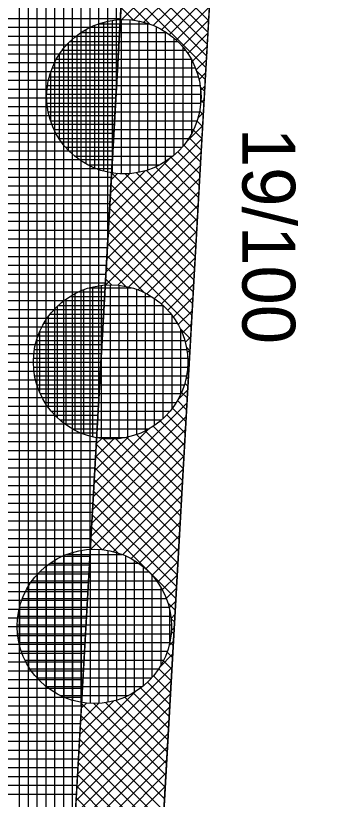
# Model space of a CAD drawing. Extents: x -565346 to -564154, y -1097386 to -1095620.
# Drawn here: x -564292.48 to -564285.01, y -1097217.11 to -1097199.33 of the extents above; entities that cross this region are included whole.
import ezdxf

# ---------------------------------------------------------------- set-up
doc = ezdxf.new("R2010")
doc.units = 0
for name, color, linetype in [('Vrstva 13', 7, 'Continuous'), ('Vrstva 40', 7, 'Continuous'), ('Vrstva 41', 7, 'Continuous'), ('Vrstva 42', 7, 'Continuous'), ('Vrstva 43', 7, 'Continuous'), ('Vrstva 44', 7, 'Continuous')]:
    doc.layers.add(name, color=color, linetype=linetype)

msp = doc.modelspace()

# ---------------------------------------------------------------- linework, layer by layer
at = {"layer": 'Vrstva 13'}
msp.add_line((-564287.03, -1097180.53), (-564291.2, -1097253.99), dxfattribs=at)
at = {"layer": 'Vrstva 41'}
msp.add_lwpolyline([(-564297.082, -1097322.329), (-564302.848, -1097333.175), (-564300.817, -1097333.615), (-564295.11, -1097322.88), (-564285.364, -1097151.156), (-564287.358, -1097151.043), (-564289.027, -1097180.417), (-564293.197, -1097253.877), (-564296.237, -1097307.437)], close=True, dxfattribs=at)
at = {"layer": 'Vrstva 42'}
for p, q in [((-564287.985, -1097197.326), (-564290.076, -1097199.417)), ((-564289.999, -1097197.539), (-564288.104, -1097199.434)), ((-564288.002, -1097197.626), (-564289.806, -1097199.429)), ((-564290.014, -1097197.807), (-564288.119, -1097199.702)), ((-564288.019, -1097197.925), (-564289.57, -1097199.476)), ((-564290.029, -1097198.075), (-564288.135, -1097199.969)), ((-564290.045, -1097198.342), (-564288.15, -1097200.237)), ((-564288.036, -1097198.225), (-564289.358, -1097199.548)), ((-564288.053, -1097198.525), (-564289.167, -1097199.639)), ((-564290.06, -1097198.61), (-564288.165, -1097200.505)), ((-564290.075, -1097198.878), (-564289.434, -1097199.519)), ((-564288.07, -1097198.825), (-564288.994, -1097199.749)), ((-564290.09, -1097199.145), (-564289.806, -1097199.429)), ((-564288.087, -1097199.125), (-564288.839, -1097199.878)), ((-564290.105, -1097199.413), (-564290.1, -1097199.418)), ((-564288.104, -1097199.425), (-564288.701, -1097200.022)), ((-564288.121, -1097199.725), (-564288.578, -1097200.182)), ((-564288.138, -1097200.024), (-564288.472, -1097200.359)), ((-564288.155, -1097200.324), (-564288.386, -1097200.555)), ((-564288.379, -1097200.574), (-564288.18, -1097200.772)), ((-564288.172, -1097200.624), (-564288.32, -1097200.772)), ((-564288.289, -1097200.946), (-564288.195, -1097201.04)), ((-564288.189, -1097200.924), (-564288.282, -1097201.017)), ((-564288.206, -1097201.224), (-564288.281, -1097201.299)), ((-564288.278, -1097201.24), (-564288.211, -1097201.308)), ((-564288.223, -1097201.524), (-564288.344, -1097201.644)), ((-564288.307, -1097201.494), (-564288.226, -1097201.575)), ((-564288.365, -1097201.719), (-564288.241, -1097201.843)), ((-564288.24, -1097201.824), (-564288.606, -1097202.189)), ((-564288.447, -1097201.92), (-564288.256, -1097202.111)), ((-564288.257, -1097202.123), (-564290.38, -1097204.246)), ((-564288.548, -1097202.101), (-564288.271, -1097202.378)), ((-564288.274, -1097202.423), (-564290.397, -1097204.546)), ((-564288.802, -1097202.413), (-564288.302, -1097202.914)), ((-564288.667, -1097202.265), (-564288.287, -1097202.646)), ((-564288.999, -1097202.582), (-564290.363, -1097203.946)), ((-564288.953, -1097202.545), (-564288.317, -1097203.181)), ((-564288.291, -1097202.723), (-564290.414, -1097204.846)), ((-564289.305, -1097202.759), (-564288.347, -1097203.717)), ((-564289.12, -1097202.661), (-564288.332, -1097203.449)), ((-564289.544, -1097202.844), (-564290.346, -1097203.647)), ((-564289.889, -1097202.907), (-564290.329, -1097203.347)), ((-564290.164, -1097202.899), (-564290.312, -1097203.047)), ((-564290.303, -1097202.892), (-564288.408, -1097204.787)), ((-564290, -1097202.913), (-564288.393, -1097204.52)), ((-564289.741, -1097202.889), (-564288.378, -1097204.252)), ((-564289.511, -1097202.836), (-564288.362, -1097203.984)), ((-564288.308, -1097203.023), (-564290.431, -1097205.146)), ((-564288.325, -1097203.323), (-564290.443, -1097205.44)), ((-564290.318, -1097203.16), (-564288.423, -1097205.055)), ((-564290.333, -1097203.428), (-564288.438, -1097205.323)), ((-564288.342, -1097203.623), (-564290.162, -1097205.443)), ((-564290.348, -1097203.695), (-564288.454, -1097205.59)), ((-564290.364, -1097203.963), (-564288.469, -1097205.858)), ((-564288.359, -1097203.923), (-564289.919, -1097205.483)), ((-564290.379, -1097204.231), (-564288.484, -1097206.125)), ((-564288.376, -1097204.222), (-564289.704, -1097205.55)), ((-564290.394, -1097204.498), (-564288.499, -1097206.393)), ((-564288.393, -1097204.522), (-564289.508, -1097205.638)), ((-564290.409, -1097204.766), (-564289.568, -1097205.608)), ((-564288.41, -1097204.822), (-564289.332, -1097205.744)), ((-564290.424, -1097205.034), (-564289.991, -1097205.467)), ((-564288.427, -1097205.122), (-564289.173, -1097205.868)), ((-564290.44, -1097205.301), (-564290.306, -1097205.435)), ((-564288.444, -1097205.422), (-564289.03, -1097206.007)), ((-564288.461, -1097205.722), (-564288.903, -1097206.163)), ((-564288.478, -1097206.022), (-564288.794, -1097206.337)), ((-564288.495, -1097206.321), (-564288.703, -1097206.53)), ((-564288.748, -1097206.428), (-564288.514, -1097206.661)), ((-564288.512, -1097206.621), (-564288.633, -1097206.742)), ((-564288.607, -1097206.851), (-564288.53, -1097206.928)), ((-564288.529, -1097206.921), (-564288.587, -1097206.979)), ((-564288.546, -1097207.221), (-564288.578, -1097207.253)), ((-564288.575, -1097207.166), (-564288.545, -1097207.196)), ((-564288.563, -1097207.521), (-564288.62, -1097207.578)), ((-564288.594, -1097207.43), (-564288.56, -1097207.464)), ((-564288.643, -1097207.663), (-564288.575, -1097207.731)), ((-564288.58, -1097207.821), (-564288.797, -1097208.038)), ((-564288.716, -1097207.873), (-564288.59, -1097207.999)), ((-564288.597, -1097208.121), (-564290.72, -1097210.244)), ((-564288.81, -1097208.062), (-564288.606, -1097208.267)), ((-564288.923, -1097208.232), (-564288.621, -1097208.534)), ((-564288.614, -1097208.421), (-564290.737, -1097210.543)), ((-564289.053, -1097208.384), (-564288.636, -1097208.802)), ((-564289.361, -1097208.643), (-564288.666, -1097209.337)), ((-564289.199, -1097208.522), (-564288.651, -1097209.07)), ((-564288.631, -1097208.72), (-564290.754, -1097210.843)), ((-564289.47, -1097208.711), (-564290.703, -1097209.944)), ((-564289.738, -1097208.831), (-564288.697, -1097209.873)), ((-564289.54, -1097208.746), (-564288.681, -1097209.605)), ((-564289.93, -1097208.888), (-564290.686, -1097209.644)), ((-564290.255, -1097208.93), (-564290.669, -1097209.344)), ((-564290.521, -1097208.913), (-564290.652, -1097209.044)), ((-564290.502, -1097208.915), (-564288.742, -1097210.676)), ((-564290.207, -1097208.928), (-564288.727, -1097210.408)), ((-564289.957, -1097208.895), (-564288.712, -1097210.14)), ((-564288.648, -1097209.02), (-564290.771, -1097211.143)), ((-564290.652, -1097209.048), (-564288.757, -1097210.943)), ((-564288.665, -1097209.32), (-564290.784, -1097211.439)), ((-564290.667, -1097209.316), (-564288.773, -1097211.211)), ((-564290.683, -1097209.584), (-564288.788, -1097211.479)), ((-564288.682, -1097209.62), (-564290.507, -1097211.445)), ((-564290.698, -1097209.851), (-564288.803, -1097211.746)), ((-564288.699, -1097209.92), (-564290.268, -1097211.489)), ((-564290.713, -1097210.119), (-564288.818, -1097212.014)), ((-564288.716, -1097210.22), (-564290.054, -1097211.558)), ((-564290.728, -1097210.387), (-564288.833, -1097212.282)), ((-564288.733, -1097210.52), (-564289.861, -1097211.647)), ((-564290.743, -1097210.654), (-564288.849, -1097212.549)), ((-564290.759, -1097210.922), (-564290.163, -1097211.517)), ((-564288.75, -1097210.819), (-564289.686, -1097211.755)), ((-564288.767, -1097211.119), (-564289.528, -1097211.88)), ((-564290.774, -1097211.19), (-564290.52, -1097211.444)), ((-564288.784, -1097211.419), (-564289.387, -1097212.022)), ((-564288.801, -1097211.719), (-564289.262, -1097212.18)), ((-564288.818, -1097212.019), (-564289.155, -1097212.355)), ((-564288.835, -1097212.319), (-564289.066, -1097212.549)), ((-564289.027, -1097212.653), (-564288.864, -1097212.817)), ((-564288.853, -1097212.619), (-564288.997, -1097212.763)), ((-564288.87, -1097212.918), (-564288.954, -1097213.003)), ((-564288.954, -1097213.01), (-564288.879, -1097213.084)), ((-564288.887, -1097213.218), (-564288.949, -1097213.281)), ((-564288.95, -1097213.296), (-564288.894, -1097213.352)), ((-564288.904, -1097213.518), (-564289, -1097213.615)), ((-564288.982, -1097213.547), (-564288.909, -1097213.62)), ((-564288.921, -1097213.818), (-564289.208, -1097214.106)), ((-564289.046, -1097213.766), (-564288.925, -1097213.887)), ((-564289.13, -1097213.965), (-564288.94, -1097214.155)), ((-564288.938, -1097214.118), (-564291.061, -1097216.241)), ((-564289.233, -1097214.144), (-564288.955, -1097214.423)), ((-564289.354, -1097214.306), (-564288.97, -1097214.69)), ((-564288.955, -1097214.418), (-564291.078, -1097216.541)), ((-564289.491, -1097214.452), (-564288.985, -1097214.958)), ((-564289.772, -1097214.67), (-564291.044, -1097215.941)), ((-564289.813, -1097214.696), (-564289.016, -1097215.493)), ((-564289.644, -1097214.583), (-564289, -1097215.226)), ((-564288.972, -1097214.718), (-564291.095, -1097216.841)), ((-564290.263, -1097214.878), (-564291.027, -1097215.641)), ((-564290.211, -1097214.864), (-564289.046, -1097216.029)), ((-564290.001, -1097214.79), (-564289.031, -1097215.761)), ((-564288.989, -1097215.017), (-564291.112, -1097217.14)), ((-564290.597, -1097214.929), (-564291.009, -1097215.341)), ((-564290.867, -1097214.916), (-564290.992, -1097215.041)), ((-564290.987, -1097214.937), (-564289.092, -1097216.832)), ((-564290.708, -1097214.933), (-564289.076, -1097216.564)), ((-564290.444, -1097214.914), (-564289.061, -1097216.296)), ((-564291.002, -1097215.204), (-564289.107, -1097217.099)), ((-564289.006, -1097215.317), (-564291.117, -1097217.429)), ((-564291.017, -1097215.472), (-564289.122, -1097217.367)), ((-564291.032, -1097215.74), (-564289.137, -1097217.635)), ((-564289.023, -1097215.617), (-564290.841, -1097217.436)), ((-564289.04, -1097215.917), (-564290.603, -1097217.48)), ((-564291.047, -1097216.007), (-564289.152, -1097217.902)), ((-564291.062, -1097216.275), (-564289.168, -1097218.17)), ((-564289.057, -1097216.217), (-564290.389, -1097217.549)), ((-564291.078, -1097216.543), (-564289.183, -1097218.438)), ((-564289.074, -1097216.517), (-564290.196, -1097217.639)), ((-564291.093, -1097216.81), (-564290.332, -1097217.571)), ((-564289.091, -1097216.817), (-564290.021, -1097217.747)), ((-564291.108, -1097217.078), (-564290.734, -1097217.452))]:
    msp.add_line(p, q, dxfattribs=at)
at = {"layer": 'Vrstva 43'}
for p, q in [((-564290.19, -1097200.905), (-564290.19, -1097068.547)), ((-564290.39, -1097204.428), (-564290.39, -1097072.067)), ((-564290.59, -1097207.951), (-564290.59, -1097075.587)), ((-564290.79, -1097211.475), (-564290.79, -1097079.106)), ((-564290.99, -1097214.998), (-564290.99, -1097082.626)), ((-564291.19, -1097218.521), (-564291.19, -1097086.146)), ((-564291.39, -1097222.044), (-564291.39, -1097089.666)), ((-564291.59, -1097225.568), (-564291.59, -1097093.186)), ((-564291.79, -1097229.091), (-564291.79, -1097096.706)), ((-564291.99, -1097232.614), (-564291.99, -1097100.226)), ((-564292.19, -1097236.137), (-564292.19, -1097103.746)), ((-564292.39, -1097239.661), (-564292.39, -1097107.266)), ((-564297.114, -1097199.39), (-564290.104, -1097199.39)), ((-564297.126, -1097199.59), (-564290.115, -1097199.59)), ((-564297.137, -1097199.79), (-564290.127, -1097199.79)), ((-564297.148, -1097199.99), (-564290.138, -1097199.99)), ((-564297.16, -1097200.19), (-564290.149, -1097200.19)), ((-564297.171, -1097200.39), (-564290.161, -1097200.39)), ((-564297.182, -1097200.59), (-564290.172, -1097200.59)), ((-564297.194, -1097200.79), (-564290.183, -1097200.79)), ((-564297.205, -1097200.99), (-564290.195, -1097200.99)), ((-564297.217, -1097201.19), (-564290.206, -1097201.19)), ((-564297.228, -1097201.39), (-564290.218, -1097201.39)), ((-564297.239, -1097201.59), (-564290.229, -1097201.59)), ((-564297.251, -1097201.79), (-564290.24, -1097201.79)), ((-564297.262, -1097201.99), (-564290.252, -1097201.99)), ((-564297.273, -1097202.19), (-564290.263, -1097202.19)), ((-564297.285, -1097202.39), (-564290.274, -1097202.39)), ((-564297.296, -1097202.59), (-564290.286, -1097202.59)), ((-564297.307, -1097202.79), (-564290.297, -1097202.79)), ((-564297.319, -1097202.99), (-564290.308, -1097202.99)), ((-564297.33, -1097203.19), (-564290.32, -1097203.19)), ((-564297.341, -1097203.39), (-564290.331, -1097203.39)), ((-564297.353, -1097203.59), (-564290.342, -1097203.59)), ((-564297.364, -1097203.79), (-564290.354, -1097203.79)), ((-564297.376, -1097203.99), (-564290.365, -1097203.99)), ((-564297.387, -1097204.19), (-564290.376, -1097204.19)), ((-564297.398, -1097204.39), (-564290.388, -1097204.39)), ((-564297.41, -1097204.59), (-564290.399, -1097204.59)), ((-564297.421, -1097204.79), (-564290.411, -1097204.79)), ((-564297.432, -1097204.99), (-564290.422, -1097204.99)), ((-564297.444, -1097205.19), (-564290.433, -1097205.19)), ((-564297.455, -1097205.39), (-564290.445, -1097205.39)), ((-564297.466, -1097205.59), (-564290.456, -1097205.59)), ((-564297.478, -1097205.79), (-564290.467, -1097205.79)), ((-564297.489, -1097205.99), (-564290.479, -1097205.99)), ((-564297.5, -1097206.19), (-564290.49, -1097206.19)), ((-564297.512, -1097206.39), (-564290.501, -1097206.39)), ((-564297.523, -1097206.59), (-564290.513, -1097206.59)), ((-564297.534, -1097206.79), (-564290.524, -1097206.79)), ((-564297.546, -1097206.99), (-564290.535, -1097206.99)), ((-564297.557, -1097207.19), (-564290.547, -1097207.19)), ((-564297.569, -1097207.39), (-564290.558, -1097207.39)), ((-564297.58, -1097207.59), (-564290.569, -1097207.59)), ((-564297.591, -1097207.79), (-564290.581, -1097207.79)), ((-564297.603, -1097207.99), (-564290.592, -1097207.99)), ((-564297.614, -1097208.19), (-564290.604, -1097208.19)), ((-564297.625, -1097208.39), (-564290.615, -1097208.39)), ((-564297.637, -1097208.59), (-564290.626, -1097208.59)), ((-564297.648, -1097208.79), (-564290.638, -1097208.79)), ((-564297.659, -1097208.99), (-564290.649, -1097208.99)), ((-564297.671, -1097209.19), (-564290.66, -1097209.19)), ((-564297.682, -1097209.39), (-564290.672, -1097209.39)), ((-564297.693, -1097209.59), (-564290.683, -1097209.59)), ((-564297.705, -1097209.79), (-564290.694, -1097209.79)), ((-564297.716, -1097209.99), (-564290.706, -1097209.99)), ((-564297.728, -1097210.19), (-564290.717, -1097210.19)), ((-564297.739, -1097210.39), (-564290.728, -1097210.39)), ((-564297.75, -1097210.59), (-564290.74, -1097210.59)), ((-564297.762, -1097210.79), (-564290.751, -1097210.79)), ((-564297.773, -1097210.99), (-564290.762, -1097210.99)), ((-564297.784, -1097211.19), (-564290.774, -1097211.19)), ((-564297.796, -1097211.39), (-564290.785, -1097211.39)), ((-564297.807, -1097211.59), (-564290.797, -1097211.59)), ((-564297.818, -1097211.79), (-564290.808, -1097211.79)), ((-564297.83, -1097211.99), (-564290.819, -1097211.99)), ((-564297.841, -1097212.19), (-564290.831, -1097212.19)), ((-564297.852, -1097212.39), (-564290.842, -1097212.39)), ((-564297.864, -1097212.59), (-564290.853, -1097212.59)), ((-564297.875, -1097212.79), (-564290.865, -1097212.79)), ((-564297.886, -1097212.99), (-564290.876, -1097212.99)), ((-564297.898, -1097213.19), (-564290.887, -1097213.19)), ((-564297.909, -1097213.39), (-564290.899, -1097213.39)), ((-564297.921, -1097213.59), (-564290.91, -1097213.59)), ((-564297.932, -1097213.79), (-564290.921, -1097213.79)), ((-564297.943, -1097213.99), (-564290.933, -1097213.99)), ((-564297.955, -1097214.19), (-564290.944, -1097214.19)), ((-564297.966, -1097214.39), (-564290.955, -1097214.39)), ((-564297.977, -1097214.59), (-564290.967, -1097214.59)), ((-564297.989, -1097214.79), (-564290.978, -1097214.79)), ((-564298, -1097214.99), (-564290.99, -1097214.99)), ((-564298.011, -1097215.19), (-564291.001, -1097215.19)), ((-564298.023, -1097215.39), (-564291.012, -1097215.39)), ((-564298.034, -1097215.59), (-564291.024, -1097215.59)), ((-564298.045, -1097215.79), (-564291.035, -1097215.79)), ((-564298.057, -1097215.99), (-564291.046, -1097215.99)), ((-564298.068, -1097216.19), (-564291.058, -1097216.19)), ((-564298.08, -1097216.39), (-564291.069, -1097216.39)), ((-564298.091, -1097216.59), (-564291.08, -1097216.59)), ((-564298.102, -1097216.79), (-564291.092, -1097216.79)), ((-564298.114, -1097216.99), (-564291.103, -1097216.99))]:
    msp.add_line(p, q, dxfattribs=at)
msp.add_lwpolyline([(-564283.37, -1096906.18), (-564284.87, -1096930.83), (-564282.373, -1096930.972), (-564294.286, -1097140.634), (-564296.782, -1097140.492), (-564297.42, -1097150.37), (-564294.347, -1097150.646), (-564303.226, -1097307.04), (-564304.096, -1097322.37), (-564304.399, -1097332.838), (-564302.848, -1097333.175), (-564297.082, -1097322.329), (-564293.197, -1097253.877), (-564289.027, -1097180.417), (-564287.358, -1097151.043), (-564285.364, -1097151.156), (-564284.798, -1097141.172), (-564286.791, -1097141.059), (-564274.888, -1096931.397), (-564272.899, -1096931.51), (-564271.475, -1096906.55)], dxfattribs=at)
at = {"layer": 'Vrstva 44'}
for p, q in [((-564290.69, -1097199.546), (-564290.69, -1097202.783)), ((-564290.593, -1097199.51), (-564289.46, -1097199.51)), ((-564290.49, -1097199.477), (-564290.49, -1097202.851)), ((-564290.29, -1097199.435), (-564290.29, -1097202.892)), ((-564290.09, -1097199.417), (-564290.09, -1097202.912)), ((-564289.89, -1097199.421), (-564289.89, -1097202.908)), ((-564289.69, -1097199.447), (-564289.69, -1097202.879)), ((-564289.49, -1097199.499), (-564289.49, -1097202.828)), ((-564289.29, -1097199.579), (-564289.29, -1097202.75)), ((-564290.998, -1097199.71), (-564289.053, -1097199.71)), ((-564290.89, -1097199.644), (-564290.89, -1097202.684)), ((-564289.09, -1097199.687), (-564289.09, -1097202.641)), ((-564291.245, -1097199.91), (-564288.807, -1097199.91)), ((-564291.09, -1097199.774), (-564291.09, -1097202.552)), ((-564288.89, -1097199.835), (-564288.89, -1097202.492)), ((-564291.422, -1097200.11), (-564288.632, -1097200.11)), ((-564291.29, -1097199.956), (-564291.29, -1097202.372)), ((-564288.69, -1097200.035), (-564288.69, -1097202.291)), ((-564291.49, -1097200.208), (-564291.49, -1097202.12)), ((-564291.552, -1097200.31), (-564288.5, -1097200.31)), ((-564288.49, -1097200.327), (-564288.49, -1097201.997)), ((-564291.69, -1097200.626), (-564291.69, -1097201.704)), ((-564291.648, -1097200.51), (-564288.405, -1097200.51)), ((-564291.716, -1097200.71), (-564288.339, -1097200.71)), ((-564291.758, -1097200.91), (-564288.297, -1097200.91)), ((-564288.29, -1097200.948), (-564288.29, -1097201.363)), ((-564291.774, -1097201.11), (-564288.278, -1097201.11)), ((-564291.768, -1097201.31), (-564288.284, -1097201.31)), ((-564291.74, -1097201.51), (-564288.313, -1097201.51)), ((-564291.688, -1097201.71), (-564288.366, -1097201.71)), ((-564291.608, -1097201.91), (-564288.445, -1097201.91)), ((-564291.496, -1097202.11), (-564288.556, -1097202.11)), ((-564291.349, -1097202.31), (-564288.706, -1097202.31)), ((-564291.143, -1097202.51), (-564288.911, -1097202.51)), ((-564290.845, -1097202.71), (-564289.211, -1097202.71)), ((-564290.118, -1097202.91), (-564289.914, -1097202.91)), ((-564290.54, -1097205.449), (-564290.54, -1097208.921)), ((-564290.34, -1097205.435), (-564290.34, -1097208.932)), ((-564290.14, -1097205.444), (-564290.14, -1097208.922)), ((-564291.14, -1097205.636), (-564291.14, -1097208.733)), ((-564290.94, -1097205.546), (-564290.94, -1097208.821)), ((-564290.802, -1097205.5), (-564289.856, -1097205.5)), ((-564290.74, -1097205.485), (-564290.74, -1097208.883)), ((-564289.94, -1097205.478), (-564289.94, -1097208.889)), ((-564289.74, -1097205.537), (-564289.74, -1097208.832)), ((-564289.54, -1097205.622), (-564289.54, -1097208.746)), ((-564291.34, -1097205.76), (-564291.34, -1097208.608)), ((-564291.254, -1097205.7), (-564289.402, -1097205.7)), ((-564289.34, -1097205.739), (-564289.34, -1097208.627)), ((-564291.54, -1097205.925), (-564291.54, -1097208.445)), ((-564291.515, -1097205.9), (-564289.14, -1097205.9)), ((-564289.14, -1097205.9), (-564289.14, -1097208.469)), ((-564291.74, -1097206.152), (-564291.74, -1097208.214)), ((-564291.698, -1097206.1), (-564288.955, -1097206.1)), ((-564288.94, -1097206.119), (-564288.94, -1097208.25)), ((-564291.836, -1097206.3), (-564288.818, -1097206.3)), ((-564291.94, -1097206.512), (-564291.94, -1097207.857)), ((-564291.935, -1097206.5), (-564288.716, -1097206.5)), ((-564288.74, -1097206.449), (-564288.74, -1097207.92)), ((-564292.006, -1097206.7), (-564288.647, -1097206.7)), ((-564292.052, -1097206.9), (-564288.602, -1097206.9)), ((-564292.074, -1097207.1), (-564288.58, -1097207.1)), ((-564292.071, -1097207.3), (-564288.58, -1097207.3)), ((-564292.046, -1097207.5), (-564288.606, -1097207.5)), ((-564291.997, -1097207.7), (-564288.656, -1097207.7)), ((-564291.923, -1097207.9), (-564288.732, -1097207.9)), ((-564291.815, -1097208.1), (-564288.836, -1097208.1)), ((-564291.673, -1097208.3), (-564288.981, -1097208.3)), ((-564291.477, -1097208.5), (-564289.175, -1097208.5)), ((-564291.196, -1097208.7), (-564289.455, -1097208.7)), ((-564290.661, -1097208.9), (-564289.993, -1097208.9)), ((-564291.19, -1097211.506), (-564291.19, -1097214.863)), ((-564290.99, -1097211.459), (-564290.99, -1097214.907)), ((-564290.79, -1097211.438), (-564290.79, -1097214.93)), ((-564290.59, -1097211.439), (-564290.59, -1097214.93)), ((-564290.39, -1097211.463), (-564290.39, -1097214.906)), ((-564291.59, -1097211.681), (-564291.59, -1097214.686)), ((-564291.39, -1097211.58), (-564291.39, -1097214.789)), ((-564291.322, -1097211.55), (-564290.074, -1097211.55)), ((-564290.19, -1097211.509), (-564290.19, -1097214.857)), ((-564289.99, -1097211.584), (-564289.99, -1097214.783)), ((-564291.79, -1097211.82), (-564291.79, -1097214.549)), ((-564291.696, -1097211.75), (-564289.695, -1097211.75)), ((-564289.79, -1097211.689), (-564289.79, -1097214.681)), ((-564289.59, -1097211.828), (-564289.59, -1097214.538)), ((-564291.99, -1097212.007), (-564291.99, -1097214.36)), ((-564291.934, -1097211.95), (-564289.456, -1097211.95)), ((-564289.39, -1097212.022), (-564289.39, -1097214.348)), ((-564292.107, -1097212.15), (-564289.286, -1097212.15)), ((-564292.232, -1097212.35), (-564289.158, -1097212.35)), ((-564292.19, -1097212.275), (-564292.19, -1097214.092)), ((-564289.19, -1097212.296), (-564289.19, -1097214.074)), ((-564292.325, -1097212.55), (-564289.067, -1097212.55)), ((-564292.391, -1097212.75), (-564289.002, -1097212.75)), ((-564292.39, -1097212.747), (-564292.39, -1097213.618)), ((-564288.99, -1097212.796), (-564288.99, -1097213.566)), ((-564292.429, -1097212.95), (-564288.962, -1097212.95)), ((-564292.444, -1097213.15), (-564288.947, -1097213.15)), ((-564292.436, -1097213.35), (-564288.955, -1097213.35)), ((-564292.406, -1097213.55), (-564288.987, -1097213.55)), ((-564292.352, -1097213.75), (-564289.042, -1097213.75)), ((-564292.267, -1097213.95), (-564289.123, -1097213.95)), ((-564292.153, -1097214.15), (-564289.239, -1097214.15)), ((-564291.999, -1097214.35), (-564289.392, -1097214.35)), ((-564291.789, -1097214.55), (-564289.605, -1097214.55)), ((-564291.474, -1097214.75), (-564289.917, -1097214.75))]:
    msp.add_line(p, q, dxfattribs=at)
for centre in [(-564290.027, -1097201.164), (-564290.326, -1097207.184), (-564290.696, -1097213.184)]:
    msp.add_circle(centre, 1.75, dxfattribs=at)

# ---------------------------------------------------------------- texts
at = {"layer": 'Vrstva 40'}
msp.add_text('19/100', height=1.2, rotation=270, dxfattribs=at).set_placement((-564287.34, -1097201.87))

doc.saveas('drawing.dxf')
